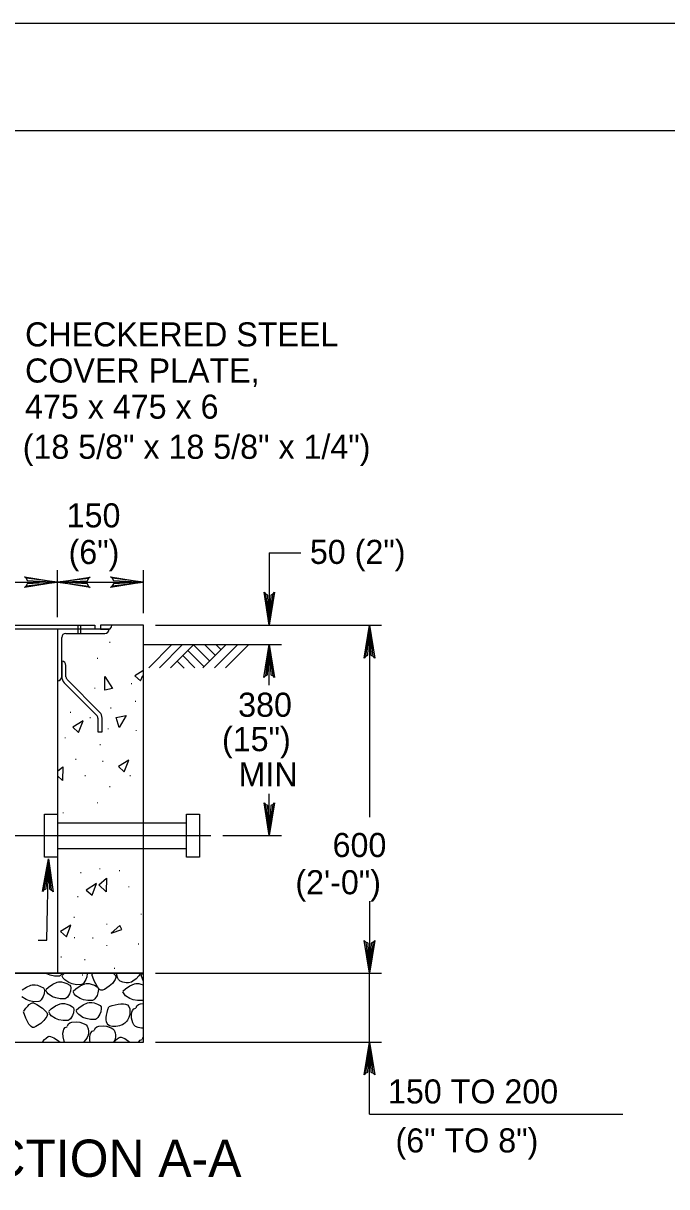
# Model space of a CAD drawing. Extents: x 638447 to 639352, y 298406 to 299000.
# Drawn here: x 638748.4 to 638838.1, y 298838.2 to 299000.5 of the extents above; entities that cross this region are included whole.
import ezdxf

# ---------------------------------------------------------------- set-up
doc = ezdxf.new("R2010")
doc.units = 0
for name, color, linetype in [('1', 7, 'Continuous'), ('2', 7, 'Continuous'), ('3', 7, 'Continuous'), ('PLT-BNDY', 7, 'Continuous')]:
    doc.layers.add(name, color=color, linetype=linetype)

msp = doc.modelspace()

# ---------------------------------------------------------------- linework, layer by layer
at = {"layer": '1'}
msp.add_lwpolyline([(639272.394625, 298421.4725), (639272.394625, 298985.4725), (638486.394625, 298985.4725), (638486.394625, 298421.4725), (639272.394625, 298421.4725), (639272.394625, 298447.8315), (639072.394625, 298447.8315), (639072.394625, 298512.509), (639272.394625, 298512.509), (639272.394625, 298541.4725), (639072.394625, 298541.4725), (639072.394625, 298421.4725), (639151.196125, 298421.4725), (639151.196125, 298447.8315), (639151.196125, 298421.4725), (639228.196125, 298421.4725), (639228.196125, 298447.8315), (639228.196125, 298435.515), (639272.394625, 298435.515)], dxfattribs=at)
at = {"layer": '2'}
for p, q in [((638782.716375, 298926.592), (638782.716375, 298916.512)), ((638782.716375, 298926.592), (638787.118375, 298926.592)), ((638753.164375, 298917.634), (638753.164375, 298924.178)), ((638765.164375, 298918.192), (638765.164375, 298924.178)), ((638746.271125, 298922.498), (638750.650125, 298922.498)), ((638753.164375, 298922.498), (638765.164375, 298922.498)), ((638760.364375, 298915.954), (638753.164375, 298915.954)), ((638753.164375, 298915.954), (638753.164375, 298908.754)), ((638756.018375, 298916.49), (638756.018375, 298915.398)), ((638756.392375, 298916.49), (638756.392375, 298915.398)), ((638766.844375, 298916.512), (638784.396375, 298916.512)), ((638766.844375, 298916.512), (638798.372375, 298916.512)), ((638796.692375, 298916.512), (638796.692375, 298889.712)), ((638753.764375, 298909.33), (638753.764375, 298914.778)), ((638754.340375, 298915.354), (638759.788375, 298915.354)), ((638765.164375, 298913.796), (638784.396375, 298913.796)), ((638765.898375, 298910.578), (638769.112375, 298913.792)), ((638766.864375, 298913.796), (638784.396375, 298913.796)), ((638767.402375, 298910.578), (638770.634375, 298913.81)), ((638768.958375, 298910.578), (638772.188375, 298913.81)), ((638771.342375, 298912.964), (638773.572375, 298910.734)), ((638772.120375, 298913.81), (638774.400375, 298911.53)), ((638773.432375, 298910.578), (638776.682375, 298913.828)), ((638773.674375, 298913.81), (638775.160375, 298912.324)), ((638775.074375, 298910.578), (638778.272375, 298913.776)), ((638775.248375, 298913.81), (638775.956375, 298913.102)), ((638776.630375, 298910.578), (638779.826375, 298913.776)), ((638782.716375, 298908.154), (638782.716375, 298913.796)), ((638753.764375, 298911.482), (638753.764375, 298909.33)), ((638769.874375, 298911.494), (638770.840375, 298910.526)), ((638770.650375, 298912.272), (638772.344375, 298910.578)), ((638754.364375, 298909.322), (638754.364375, 298910.906)), ((638754.116375, 298908.482), (638758.636375, 298903.962)), ((638759.052375, 298904.394), (638754.532375, 298908.914)), ((638758.804375, 298903.556), (638758.804375, 298901.642)), ((638759.404375, 298901.642), (638759.404375, 298903.546)), ((638758.804375, 298901.642), (638759.404375, 298901.642)), ((638782.716375, 298887.154), (638782.716375, 298892.95875)), ((638753.164375, 298888.954), (638765.164375, 298888.954)), ((638765.164375, 298888.954), (638771.164375, 298888.954)), ((638694.150375, 298887.154), (638774.544375, 298887.154)), ((638776.224375, 298887.154), (638784.396375, 298887.154)), ((638753.164375, 298885.354), (638765.164375, 298885.354)), ((638765.164375, 298885.354), (638771.164375, 298885.354)), ((638796.692375, 298878.02325), (638796.692375, 298867.954)), ((638711.164375, 298867.954), (638765.164375, 298867.954)), ((638766.844375, 298867.954), (638798.372375, 298867.954)), ((638796.692375, 298848.274), (638796.692375, 298867.954)), ((638766.844375, 298858.354), (638798.372375, 298858.354)), ((638796.692375, 298848.274), (638832.009255, 298848.274))]:
    msp.add_line(p, q, dxfattribs=at)
for points in [[(638748.804375, 298923.046), (638748.968375, 298922.73), (638753.164375, 298922.498), (638748.804375, 298923.046), (638748.582375, 298923.236), (638753.164375, 298922.498), (638748.970375, 298922.29), (638748.818375, 298921.978), (638753.164375, 298922.498), (638748.582375, 298921.77), (638748.818375, 298921.978)], [(638757.524375, 298921.952), (638757.360375, 298922.266), (638753.164375, 298922.498), (638757.524375, 298921.952), (638757.746375, 298921.76), (638753.164375, 298922.498), (638757.358375, 298922.706), (638757.510375, 298923.018), (638753.164375, 298922.498), (638757.746375, 298923.226), (638757.510375, 298923.018)], [(638760.804375, 298923.046), (638760.968375, 298922.73), (638765.164375, 298922.498), (638760.804375, 298923.046), (638760.582375, 298923.236), (638765.164375, 298922.498), (638760.970375, 298922.29), (638760.818375, 298921.978), (638765.164375, 298922.498), (638760.582375, 298921.77), (638760.818375, 298921.978)], [(638783.264375, 298920.87), (638782.948375, 298920.708), (638782.716375, 298916.512), (638783.264375, 298920.87), (638783.454375, 298921.094), (638782.716375, 298916.512), (638782.508375, 298920.704), (638782.196375, 298920.858), (638782.716375, 298916.512), (638781.988375, 298921.094), (638782.196375, 298920.858)], [(638760.364375, 298915.954), (638753.164375, 298915.954), (638753.164375, 298867.954), (638765.164375, 298867.954), (638765.164375, 298915.954), (638765.164375, 298915.954)], [(638765.164375, 298915.954), (638765.164375, 298916.512), (638759.164375, 298916.512), (638759.164375, 298915.954), (638760.364375, 298915.954)], [(638796.146375, 298912.152), (638796.462375, 298912.314), (638796.692375, 298916.512), (638796.146375, 298912.152), (638795.954375, 298911.928), (638796.692375, 298916.512), (638796.900375, 298912.318), (638797.212375, 298912.164), (638796.692375, 298916.512), (638797.420375, 298911.928), (638797.212375, 298912.164)], [(638782.168375, 298909.436), (638782.484375, 298909.6), (638782.716375, 298913.796), (638782.168375, 298909.436), (638781.978375, 298909.214), (638782.716375, 298913.796), (638782.924375, 298909.602), (638783.236375, 298909.45), (638782.716375, 298913.796), (638783.444375, 298909.214), (638783.236375, 298909.45)], [(638765.072375, 298910.156), (638763.958375, 298909.46)], [(638763.958375, 298909.46), (638764.774375, 298908.728)], [(638764.774375, 298908.728), (638765.062375, 298909.48)], [(638753.174375, 298896.124), (638753.914375, 298896.764)], [(638753.914375, 298896.764), (638753.866375, 298894.82)], [(638753.866375, 298894.82), (638753.168375, 298895.5)], [(638783.264375, 298891.514), (638782.948375, 298891.352), (638782.716375, 298887.154), (638783.264375, 298891.514), (638783.454375, 298891.738), (638782.716375, 298887.154), (638782.508375, 298891.348), (638782.196375, 298891.502), (638782.716375, 298887.154), (638781.988375, 298891.738), (638782.196375, 298891.502)], [(638750.494375, 298872.588), (638751.694375, 298872.588), (638751.926375, 298883.914)], [(638751.290375, 298879.568), (638751.608375, 298879.724), (638751.926375, 298883.914), (638751.290375, 298879.568), (638751.094375, 298879.348), (638751.926375, 298883.914), (638752.048375, 298879.718), (638752.356375, 298879.558), (638751.926375, 298883.914), (638752.560375, 298879.318), (638752.356375, 298879.558)], [(638797.240375, 298872.314), (638796.924375, 298872.152), (638796.692375, 298867.954), (638797.240375, 298872.314), (638797.432375, 298872.538), (638796.692375, 298867.954), (638796.486375, 298872.148), (638796.174375, 298872.302), (638796.692375, 298867.954), (638795.964375, 298872.538), (638796.174375, 298872.302)], [(638751.692375, 298867.852), (638751.536375, 298867.954)], [(638752.152375, 298867.676), (638751.692375, 298867.852)], [(638752.768375, 298867.546), (638752.152375, 298867.676)], [(638753.440375, 298867.568), (638752.768375, 298867.546)], [(638753.600375, 298867.65), (638753.440375, 298867.568)], [(638753.762375, 298867.81), (638753.600375, 298867.65)], [(638753.852375, 298867.954), (638753.762375, 298867.81)], [(638753.826375, 298867.642), (638754.152375, 298867.954)], [(638753.966375, 298867.282), (638753.826375, 298867.566)], [(638754.182375, 298867.036), (638753.966375, 298867.282)], [(638757.270375, 298867.436), (638757.132375, 298867.074)], [(638757.336375, 298867.898), (638757.270375, 298867.436)], [(638757.326375, 298867.954), (638757.336375, 298867.898)], [(638758.312375, 298866.878), (638757.984375, 298867.764)], [(638758.022375, 298867.822), (638758.120375, 298867.954)], [(638760.950375, 298867.954), (638761.260375, 298867.648)], [(638761.330375, 298867.374), (638761.238375, 298867.084)], [(638761.260375, 298867.648), (638761.330375, 298867.374)], [(638761.532375, 298867.374), (638761.396375, 298867.954)], [(638761.680375, 298867.084), (638761.532375, 298867.374)], [(638764.540375, 298867.606), (638764.138375, 298867.184)], [(638764.766375, 298867.916), (638764.540375, 298867.606)], [(638764.784375, 298867.954), (638764.766375, 298867.916)], [(638765.164375, 298866.814), (638764.842375, 298867.678)], [(638764.882375, 298867.736), (638765.042375, 298867.954)], [(638748.234375, 298865.622), (638748.838375, 298866.022)], [(638748.838375, 298866.022), (638749.464375, 298866.304)], [(638749.464375, 298866.304), (638749.668375, 298866.354)], [(638749.668375, 298866.354), (638750.066375, 298866.35)], [(638750.066375, 298866.35), (638750.380375, 298866.286)], [(638750.380375, 298866.286), (638750.830375, 298866.122)], [(638750.830375, 298866.122), (638751.208375, 298865.916)], [(638751.208375, 298865.916), (638751.342375, 298865.746)], [(638751.342375, 298865.746), (638751.384375, 298865.53)], [(638751.544375, 298865.672), (638751.904375, 298866.018)], [(638751.684375, 298865.312), (638751.544375, 298865.596)], [(638751.904375, 298866.018), (638752.508375, 298866.418)], [(638752.508375, 298866.418), (638753.134375, 298866.7)], [(638753.134375, 298866.7), (638753.338375, 298866.752)], [(638753.338375, 298866.752), (638753.738375, 298866.748)], [(638753.738375, 298866.748), (638754.050375, 298866.682)], [(638754.050375, 298866.682), (638754.500375, 298866.518)], [(638754.774375, 298866.648), (638754.182375, 298867.036)], [(638754.500375, 298866.518), (638754.878375, 298866.312)], [(638755.232375, 298866.472), (638754.774375, 298866.648)], [(638754.878375, 298866.312), (638755.014375, 298866.142)], [(638755.054375, 298865.928), (638754.988375, 298865.468)], [(638755.014375, 298866.142), (638755.054375, 298865.928)], [(638755.848375, 298866.342), (638755.232375, 298866.472)], [(638755.384375, 298865.432), (638755.746375, 298865.778)], [(638755.746375, 298865.778), (638756.350375, 298866.178)], [(638756.520375, 298866.364), (638755.848375, 298866.342)], [(638756.350375, 298866.178), (638756.974375, 298866.46)], [(638756.680375, 298866.446), (638756.520375, 298866.364)], [(638756.842375, 298866.606), (638756.680375, 298866.446)], [(638757.132375, 298867.074), (638756.842375, 298866.606)], [(638756.974375, 298866.46), (638757.180375, 298866.51)], [(638757.180375, 298866.51), (638757.578375, 298866.506)], [(638757.578375, 298866.506), (638757.890375, 298866.442)], [(638757.890375, 298866.442), (638758.340375, 298866.278)], [(638758.748375, 298866.044), (638758.312375, 298866.878)], [(638758.340375, 298866.278), (638758.720375, 298866.072)], [(638758.720375, 298866.072), (638758.854375, 298865.902)], [(638759.054375, 298865.674), (638758.748375, 298866.044)], [(638758.896375, 298865.686), (638758.828375, 298865.226)], [(638758.854375, 298865.902), (638758.896375, 298865.686)], [(638759.224375, 298865.572), (638759.054375, 298865.674)], [(638759.436375, 298865.578), (638759.224375, 298865.572)], [(638759.722375, 298865.688), (638759.436375, 298865.578)], [(638760.396375, 298866.132), (638759.722375, 298865.688)], [(638760.828375, 298866.528), (638760.396375, 298866.132)], [(638761.238375, 298867.084), (638760.828375, 298866.528)], [(638761.898375, 298866.87), (638761.680375, 298867.084)], [(638762.292375, 298866.71), (638761.898375, 298866.87)], [(638762.760375, 298866.632), (638762.292375, 298866.71)], [(638762.314375, 298865.432), (638762.676375, 298865.778)], [(638762.676375, 298865.778), (638763.280375, 298866.178)], [(638763.080375, 298866.638), (638762.760375, 298866.632)], [(638763.482375, 298866.73), (638763.080375, 298866.638)], [(638763.280375, 298866.178), (638763.904375, 298866.46)], [(638763.680375, 298866.83), (638763.482375, 298866.73)], [(638764.138375, 298867.184), (638763.680375, 298866.83)], [(638763.904375, 298866.46), (638764.110375, 298866.51)], [(638764.110375, 298866.51), (638764.508375, 298866.506)], [(638764.508375, 298866.506), (638764.820375, 298866.442)], [(638764.820375, 298866.442), (638765.164375, 298866.316)], [(638748.820375, 298864.282), (638748.228375, 298864.668)], [(638749.280375, 298864.106), (638748.820375, 298864.282)], [(638749.896375, 298863.976), (638749.280375, 298864.106)], [(638750.568375, 298863.996), (638749.896375, 298863.976)], [(638750.728375, 298864.08), (638750.568375, 298863.996)], [(638750.890375, 298864.238), (638750.728375, 298864.08)], [(638751.180375, 298864.706), (638750.890375, 298864.238)], [(638751.318375, 298865.07), (638751.180375, 298864.706)], [(638751.384375, 298865.53), (638751.318375, 298865.07)], [(638751.900375, 298865.066), (638751.684375, 298865.312)], [(638752.492375, 298864.678), (638751.900375, 298865.066)], [(638752.950375, 298864.502), (638752.492375, 298864.678)], [(638753.566375, 298864.372), (638752.950375, 298864.502)], [(638754.238375, 298864.394), (638753.566375, 298864.372)], [(638754.398375, 298864.476), (638754.238375, 298864.394)], [(638754.560375, 298864.636), (638754.398375, 298864.476)], [(638754.850375, 298865.104), (638754.560375, 298864.636)], [(638754.988375, 298865.468), (638754.850375, 298865.104)], [(638755.524375, 298865.072), (638755.384375, 298865.354)], [(638755.740375, 298864.824), (638755.524375, 298865.072)], [(638756.332375, 298864.438), (638755.740375, 298864.824)], [(638756.792375, 298864.262), (638756.332375, 298864.438)], [(638757.406375, 298864.132), (638756.792375, 298864.262)], [(638758.080375, 298864.152), (638757.406375, 298864.132)], [(638758.238375, 298864.236), (638758.080375, 298864.152)], [(638758.400375, 298864.394), (638758.238375, 298864.236)], [(638758.692375, 298864.862), (638758.400375, 298864.394)], [(638758.828375, 298865.226), (638758.692375, 298864.862)], [(638762.454375, 298865.072), (638762.314375, 298865.354)], [(638762.670375, 298864.824), (638762.454375, 298865.072)], [(638763.262375, 298864.438), (638762.670375, 298864.824)], [(638763.722375, 298864.262), (638763.262375, 298864.438)], [(638764.336375, 298864.132), (638763.722375, 298864.262)], [(638765.010375, 298864.152), (638764.336375, 298864.132)], [(638765.164375, 298864.232), (638765.010375, 298864.152)], [(638748.760375, 298861.708), (638748.432375, 298862.594)], [(638748.470375, 298862.652), (638748.782375, 298863.078)], [(638748.782375, 298863.078), (638749.036375, 298863.384)], [(638749.036375, 298863.384), (638749.234375, 298863.58)], [(638749.234375, 298863.58), (638749.532375, 298863.78)], [(638749.532375, 298863.78), (638749.680375, 298863.822)], [(638749.680375, 298863.822), (638749.828375, 298863.816)], [(638749.828375, 298863.816), (638750.318375, 298863.618)], [(638750.318375, 298863.618), (638751.102375, 298863.08)], [(638751.102375, 298863.08), (638751.708375, 298862.478)], [(638751.708375, 298862.478), (638751.778375, 298862.204)], [(638751.954375, 298862.642), (638752.316375, 298862.988)], [(638752.094375, 298862.282), (638751.954375, 298862.566)], [(638752.316375, 298862.988), (638752.920375, 298863.388)], [(638752.920375, 298863.388), (638753.544375, 298863.67)], [(638753.544375, 298863.67), (638753.750375, 298863.722)], [(638753.750375, 298863.722), (638754.148375, 298863.718)], [(638754.148375, 298863.718), (638754.460375, 298863.652)], [(638754.460375, 298863.652), (638754.912375, 298863.488)], [(638754.912375, 298863.488), (638755.290375, 298863.282)], [(638755.400375, 298862.438), (638755.262375, 298862.074)], [(638755.290375, 298863.282), (638755.424375, 298863.112)], [(638755.466375, 298862.898), (638755.400375, 298862.438)], [(638755.424375, 298863.112), (638755.466375, 298862.898)], [(638755.782375, 298862.798), (638756.142375, 298863.144)], [(638755.922375, 298862.438), (638755.782375, 298862.722)], [(638756.136375, 298862.192), (638755.922375, 298862.438)], [(638756.142375, 298863.144), (638756.746375, 298863.544)], [(638756.746375, 298863.544), (638757.372375, 298863.826)], [(638757.372375, 298863.826), (638757.576375, 298863.878)], [(638757.576375, 298863.878), (638757.974375, 298863.874)], [(638757.974375, 298863.874), (638758.288375, 298863.808)], [(638758.288375, 298863.808), (638758.738375, 298863.644)], [(638758.738375, 298863.644), (638759.116375, 298863.438)], [(638759.226375, 298862.594), (638759.088375, 298862.23)], [(638759.116375, 298863.438), (638759.250375, 298863.268)], [(638759.292375, 298863.054), (638759.226375, 298862.594)], [(638759.250375, 298863.268), (638759.292375, 298863.054)], [(638763.512375, 298862.182), (638763.568375, 298862.526)], [(638763.568375, 298862.526), (638763.646375, 298862.746)], [(638763.646375, 298862.746), (638763.830375, 298862.986)], [(638763.830375, 298862.986), (638764.094375, 298863.078)], [(638764.134375, 298863.136), (638764.240375, 298863.43)], [(638764.240375, 298863.43), (638764.472375, 298863.604)], [(638764.472375, 298863.604), (638764.754375, 298863.7)], [(638764.754375, 298863.7), (638765.164375, 298863.732)], [(638749.196375, 298860.874), (638748.760375, 298861.708)], [(638749.502375, 298860.504), (638749.196375, 298860.874)], [(638750.844375, 298860.962), (638750.170375, 298860.518)], [(638751.276375, 298861.358), (638750.844375, 298860.962)], [(638751.686375, 298861.914), (638751.276375, 298861.358)], [(638751.778375, 298862.204), (638751.686375, 298861.914)], [(638752.310375, 298862.036), (638752.094375, 298862.282)], [(638752.902375, 298861.648), (638752.310375, 298862.036)], [(638753.362375, 298861.472), (638752.902375, 298861.648)], [(638753.976375, 298861.342), (638753.362375, 298861.472)], [(638754.650375, 298861.364), (638753.976375, 298861.342)], [(638754.568375, 298860.556), (638754.674375, 298860.848)], [(638754.810375, 298861.446), (638754.650375, 298861.364)], [(638754.674375, 298860.848), (638754.906375, 298861.024)], [(638754.970375, 298861.606), (638754.810375, 298861.446)], [(638754.906375, 298861.024), (638755.188375, 298861.118)], [(638755.262375, 298862.074), (638754.970375, 298861.606)], [(638755.188375, 298861.118), (638755.792375, 298861.166)], [(638755.792375, 298861.166), (638756.274375, 298861.112)], [(638756.728375, 298861.804), (638756.136375, 298862.192)], [(638756.274375, 298861.112), (638756.918375, 298860.9)], [(638757.188375, 298861.628), (638756.728375, 298861.804)], [(638756.918375, 298860.9), (638757.162375, 298860.742)], [(638757.162375, 298860.742), (638757.320375, 298860.556)], [(638757.804375, 298861.498), (638757.188375, 298861.628)], [(638758.476375, 298861.52), (638757.804375, 298861.498)], [(638758.636375, 298861.602), (638758.476375, 298861.52)], [(638758.798375, 298861.762), (638758.636375, 298861.602)], [(638759.088375, 298862.23), (638758.798375, 298861.762)], [(638763.522375, 298861.68), (638763.512375, 298862.182)], [(638763.672375, 298861.044), (638763.522375, 298861.68)], [(638763.818375, 298860.754), (638763.672375, 298861.044)], [(638764.036375, 298860.538), (638763.818375, 298860.754)], [(638749.672375, 298860.402), (638749.502375, 298860.504)], [(638749.884375, 298860.408), (638749.672375, 298860.402)], [(638750.170375, 298860.518), (638749.884375, 298860.408)], [(638751.588375, 298858.92), (638751.886375, 298859.12)], [(638751.886375, 298859.12), (638752.034375, 298859.16)], [(638752.034375, 298859.16), (638752.182375, 298859.154)], [(638752.182375, 298859.154), (638752.672375, 298858.958)], [(638753.946375, 298859.6), (638754.002375, 298859.944)], [(638753.956375, 298859.098), (638753.946375, 298859.6)], [(638754.106375, 298858.462), (638753.956375, 298859.098)], [(638754.002375, 298859.944), (638754.080375, 298860.164)], [(638754.080375, 298860.164), (638754.264375, 298860.404)], [(638754.264375, 298860.404), (638754.528375, 298860.498)], [(638757.320375, 298860.556), (638757.456375, 298860.206)], [(638757.472375, 298859.31), (638757.340375, 298859.004)], [(638757.456375, 298860.206), (638757.512375, 298859.898)], [(638757.520375, 298859.658), (638757.472375, 298859.31)], [(638757.512375, 298859.898), (638757.520375, 298859.658)], [(638757.696375, 298859.058), (638757.750375, 298859.402)], [(638757.750375, 298859.402), (638757.830375, 298859.624)], [(638757.830375, 298859.624), (638758.014375, 298859.862)], [(638758.014375, 298859.862), (638758.278375, 298859.956)], [(638758.318375, 298860.014), (638758.422375, 298860.308)], [(638758.422375, 298860.308), (638758.656375, 298860.482)], [(638758.656375, 298860.482), (638758.938375, 298860.578)], [(638758.938375, 298860.578), (638759.540375, 298860.626)], [(638759.540375, 298860.626), (638760.022375, 298860.57)], [(638760.022375, 298860.57), (638760.668375, 298860.358)], [(638760.668375, 298860.358), (638760.910375, 298860.2)], [(638760.910375, 298860.2), (638761.070375, 298860.014)], [(638761.070375, 298860.014), (638761.206375, 298859.664)], [(638761.206375, 298859.664), (638761.260375, 298859.356)], [(638761.270375, 298859.116), (638761.222375, 298858.768)], [(638761.260375, 298859.356), (638761.270375, 298859.116)], [(638764.430375, 298860.38), (638764.036375, 298860.538)], [(638764.898375, 298860.302), (638764.430375, 298860.38)], [(638765.164375, 298860.306), (638764.898375, 298860.302)], [(638765.118375, 298859.048), (638765.164375, 298859.084)], [(638751.092375, 298858.354), (638751.138375, 298858.416)], [(638751.138375, 298858.416), (638751.390375, 298858.724)], [(638751.390375, 298858.724), (638751.588375, 298858.92)], [(638752.672375, 298858.958), (638753.456375, 298858.42)], [(638753.456375, 298858.42), (638753.520375, 298858.356)], [(638754.160375, 298858.354), (638754.106375, 298858.462)], [(638757.114375, 298858.694), (638756.790375, 298858.354)], [(638757.340375, 298859.004), (638757.114375, 298858.694)], [(638757.706375, 298858.556), (638757.696375, 298859.058)], [(638757.752375, 298858.354), (638757.706375, 298858.556)], [(638761.090375, 298858.464), (638761.010375, 298858.354)], [(638761.086375, 298858.354), (638761.290375, 298858.6)], [(638761.222375, 298858.768), (638761.090375, 298858.464)], [(638761.290375, 298858.6), (638761.486375, 298858.796)], [(638761.486375, 298858.796), (638761.784375, 298858.996)], [(638761.784375, 298858.996), (638761.934375, 298859.036)], [(638761.934375, 298859.036), (638762.080375, 298859.03)], [(638762.080375, 298859.03), (638762.570375, 298858.834)], [(638762.570375, 298858.834), (638763.268375, 298858.354)], [(638764.522375, 298858.354), (638764.526375, 298858.364)], [(638764.526375, 298858.364), (638764.708375, 298858.604)], [(638764.708375, 298858.604), (638764.974375, 298858.698)], [(638765.012375, 298858.756), (638765.118375, 298859.048)], [(638796.146375, 298853.996), (638796.462375, 298854.158), (638796.692375, 298858.354), (638796.146375, 298853.996), (638795.954375, 298853.772), (638796.692375, 298858.354), (638796.900375, 298854.162), (638797.212375, 298854.008), (638796.692375, 298858.354), (638797.420375, 298853.772), (638797.212375, 298854.008)]]:
    msp.add_lwpolyline(points, dxfattribs=at)
for points in [[(638717.902375, 298915.954), (638717.902375, 298916.512), (638758.388375, 298916.512), (638758.388375, 298915.954)], [(638760.838375, 298907.66), (638759.794375, 298907.42), (638759.758375, 298909.328)], [(638756.746375, 298903.172), (638755.306375, 298902.272), (638756.122375, 298901.54)], [(638761.366375, 298903.64), (638762.770375, 298903.916), (638761.762375, 298902.248)], [(638763.118375, 298897.676), (638761.678375, 298896.776), (638762.494375, 298896.044)], [(638751.364375, 298884.154), (638751.364375, 298890.154), (638753.164375, 298890.154), (638753.164375, 298884.154)], [(638771.164375, 298884.154), (638771.164375, 298890.154), (638772.964375, 298890.154), (638772.964375, 298884.154)], [(638758.624375, 298880.456), (638757.184375, 298879.556), (638758.000375, 298878.824)], [(638758.936375, 298880.3), (638760.016375, 298881.236), (638759.968375, 298879.292)], [(638755.036375, 298874.672), (638753.596375, 298873.772), (638754.412375, 298873.04)], [(638762.140375, 298874.06), (638761.888375, 298874.636), (638760.652375, 298873.568)], [(638711.164375, 298867.954), (638711.164375, 298858.354), (638765.164375, 298858.354), (638765.164375, 298867.954)]]:
    msp.add_lwpolyline(points, close=True, dxfattribs=at)
for centre, radius, start, end in [((638759.788421, 298915.930868), 0.576, 270, 0), ((638760.156418, 298916.483002), 0.590014, 290.64261389, 356.09181111), ((638754.340421, 298914.778868), 0.576, 90, 180), ((638753.788469, 298910.906372), 0.576, 0, 90), ((638753.188421, 298909.330868), 0.576, 270, 0), ((638754.964469, 298909.330884), 1.2, 180, 225), ((638754.940469, 298909.320959), 0.576, 180, 225), ((638758.228469, 298903.555241), 0.576, 0, 45), ((638758.204469, 298903.545315), 1.2, 0, 45)]:
    msp.add_arc(centre, radius, start, end, dxfattribs=at)
msp.add_spline([(638760.364375, 298863.334), (638763.118375, 298863.334), (638763.136375, 298861.782), (638762.052375, 298860.696), (638760.268375, 298860.736), (638760.326375, 298863.276)], degree=3, dxfattribs=at)
at = {"layer": 'PLT-BNDY'}
msp.add_lwpolyline([(638447.394625, 299000.4725), (639288.394625, 299000.4725), (639288.394625, 298406.4725), (638447.394625, 298406.4725)], close=True, dxfattribs=at)

# ---------------------------------------------------------------- texts
at = {"layer": '1'}
for s, p in [('(18 5/8" x 18 5/8" x 1/4")', (638748.33273, 298939.71325)), ('(6")', (638754.721875, 298925.03775)), ('(15")', (638776.122375, 298898.933)), ('(6" TO 8")', (638800.320375, 298842.957))]:
    msp.add_text(s, height=3.36, dxfattribs=at).set_placement(p)
at = {"layer": '2'}
for p in [(638760.250375, 298914.044), (638758.534375, 298911.8), (638758.174375, 298907.636), (638763.310375, 298908.26), (638760.394375, 298904.876), (638763.850375, 298905.812), (638754.802375, 298904.252), (638757.514375, 298903.52), (638760.058375, 298901.96), (638763.934375, 298901.732), (638754.034375, 298900.712), (638758.918375, 298899.752), (638755.510375, 298897.7), (638759.278375, 298897.424), (638756.830375, 298895.444), (638763.118375, 298895.444), (638760.250375, 298893.884), (638758.534375, 298891.64), (638753.770375, 298890.248), (638756.212375, 298881.896), (638758.888375, 298882.436), (638761.612375, 298882.172), (638755.828375, 298878.56), (638762.932375, 298879.916), (638755.276375, 298875.68), (638764.636375, 298876.112), (638759.872375, 298874.72), (638755.360375, 298872.848), (638757.904375, 298872.776), (638764.276375, 298871.948), (638759.872375, 298871.744), (638753.488375, 298870.124), (638756.788375, 298869.776), (638756.476375, 298867.64), (638760.904375, 298868.564), (638763.616375, 298867.832)]:
    msp.add_text('.', height=1.116, dxfattribs=at).set_placement(p)
at = {"layer": '3'}
for s, height, p in [('CHECKERED STEEL', 3.359988, (638748.657125, 298955.39375)), ('COVER PLATE,', 3.359988, (638748.657125, 298950.35375)), ('475 x 475 x 6', 3.359988, (638748.657125, 298945.31375)), ('150', 3.36, (638754.462875, 298930.1505)), ('50 (2")', 3.36, (638788.380375, 298925.054)), ('380', 3.36, (638778.374625, 298903.73275)), ('MIN', 3.36, (638778.427875, 298894.01725)), ('600', 3.36, (638791.547625, 298884.164)), ('(2\'-0")', 3.36, (638786.352875, 298878.969)), ('150 TO 200', 3.36, (638799.271625, 298849.78725)), ('SECTION A-A', 5.2000005, (638734.404875, 298839.55))]:
    msp.add_text(s, height=height, dxfattribs=at).set_placement(p)

doc.saveas('drawing.dxf')
